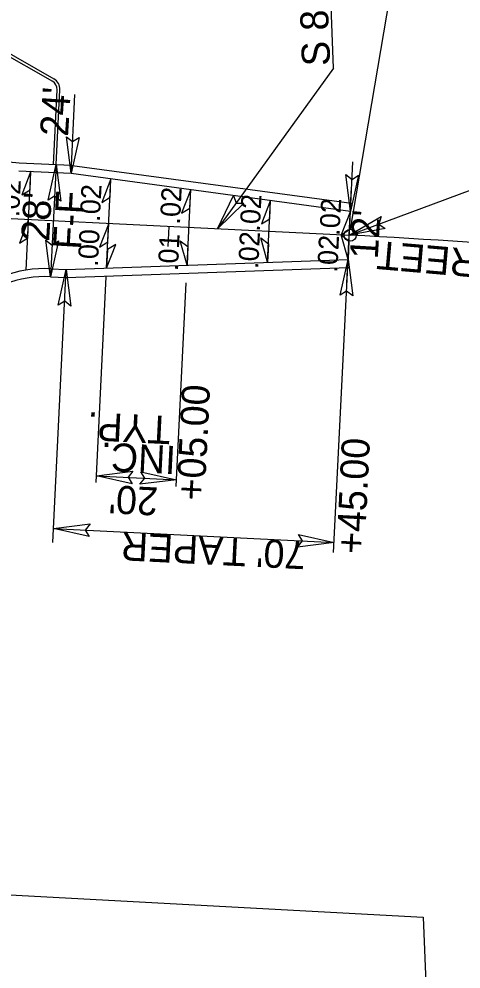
# Model space of a CAD drawing. Extents: x 1627861 to 1629601, y 761281 to 766239.
# Drawn here: x 1628433.8 to 1628544, y 764815.3 to 765051.9 of the extents above; entities that cross this region are included whole.
import ezdxf

# ---------------------------------------------------------------- set-up
doc = ezdxf.new("R2010")
doc.units = 0
for name, color, linetype in [('Cogo Default Point CELL', 7, 'Continuous'), ('Exist Other Culture Sign Leader', 7, 'Continuous'), ('Exist Property Tie Line Text', 7, 'Continuous'), ('Exist Right of Way Line Leader', 7, 'Continuous'), ('Exist Right of Way Monument Text', 7, 'Continuous'), ('Exist Utilities Gas Meter CELL', 7, 'Continuous'), ('Exist Utilities Gas Meter Cogo Elevation', 7, 'Continuous'), ('Exist Utilities Gas Meter Cogo Number', 7, 'Continuous'), ('Exist Utilities Power UG Cable SUE LOS B Cogo Point CELL', 7, 'Continuous'), ('Exist Utilities Telephone UG Cable SUE LOS B Cogo Number', 7, 'Continuous'), ('Exist Utilities Telephone UG Cable SUE LOS B Cogo Point CELL', 7, 'Continuous'), ('Exist Utilities Water UG Line SUE LOS B Cogo Number', 7, 'Continuous'), ('Scratch_Level_0', 7, 'Continuous'), ('Typical Terminator CELL', 7, 'Continuous')]:
    doc.layers.add(name, color=color, linetype=linetype)

msp = doc.modelspace()

# ---------------------------------------------------------------- linework, layer by layer
at = {"layer": 'Exist Property Tie Line Text'}
msp.add_line((1628471.18, 765000.29), (1628470.94, 764995.3), dxfattribs=at)
at = {"layer": 'Exist Right of Way Line Leader'}
for p, q in [((1628512.23, 765039.73), (1628509.44, 765110.32)), ((1628516.43, 764999.57), (1628528.34, 765069.48)), ((1628512.23, 765039.73), (1628483.32, 764999.7)), ((1628379.89, 764836.53), (1628534.55, 764828.18)), ((1628534.55, 764828.18), (1628539.7, 764697.65))]:
    msp.add_line(p, q, dxfattribs=at)
msp.add_circle((1628516.35, 764998.07), 1.5, dxfattribs=at)
at = {"layer": 'Exist Right of Way Monument Text'}
for p, q in [((1628433.78, 765014.15), (1628442.99, 765013.69)), ((1628442.99, 765013.69), (1628446.8, 765013.51)), ((1628446.8, 765013.51), (1628516.42, 765004.09)), ((1628445.62, 764989.53), (1628515.83, 764992.06)), ((1628441.81, 764989.72), (1628445.62, 764989.53))]:
    msp.add_line(p, q, dxfattribs=at)
msp.add_arc((1628440.34, 764959.76), 30, 87.1852, 182.2582, dxfattribs=at)
at = {"layer": 'Exist Utilities Gas Meter CELL'}
msp.add_line((1628371.3, 765005.2), (1628516.35, 764998.07), dxfattribs=at)
msp.add_arc((1628450.06, 763649.7), 1350, 82.22219, 87.18524, dxfattribs=at)
at = {"layer": 'Exist Utilities Gas Meter Cogo Elevation'}
msp.add_line((1628433.87, 765016.14), (1628443.09, 765015.69), dxfattribs=at)
for centre, start, end in [((1628435.25, 765044.11), 185.0968, 267.1852), ((1628440.34, 764959.76), 87.1852, 182.2582)]:
    msp.add_arc(centre, 28, start, end, dxfattribs=at)
at = {"layer": 'Exist Utilities Gas Meter Cogo Number'}
for points in [[(1628448.79, 765022.42), (1628446.8, 765013.51), (1628445.65, 765022.62), (1628447.19, 765021.4)], [(1628441.1, 765006.78), (1628443.09, 765015.69), (1628444.24, 765006.57), (1628442.7, 765007.8)], [(1628518.41, 765013), (1628516.42, 765004.09), (1628515.27, 765013.21), (1628516.81, 765011.98)], [(1628489.84, 765006.08), (1628483.32, 764999.7), (1628487.32, 765007.97), (1628487.94, 765006.1)], [(1628525.1, 764999.77), (1628516.13, 764998.08), (1628524.05, 765002.74), (1628523.53, 765000.84)], [(1628443.7, 764996.64), (1628441.71, 764987.72), (1628440.56, 764996.84), (1628442.1, 764995.61)], [(1628513.84, 764983.15), (1628515.83, 764992.06), (1628516.99, 764982.95), (1628515.44, 764984.17)], [(1628443.63, 764980.62), (1628445.62, 764989.53), (1628446.78, 764980.42), (1628445.23, 764981.64)], [(1628462.02, 764936.17), (1628453.11, 764938.16), (1628462.23, 764939.31), (1628461, 764937.77)], [(1628464.17, 764939.17), (1628473.08, 764937.18), (1628463.97, 764936.02), (1628465.19, 764937.56)], [(1628451.36, 764923), (1628442.45, 764924.99), (1628451.57, 764926.15), (1628450.34, 764924.61)], [(1628503.45, 764923.55), (1628512.37, 764921.56), (1628503.25, 764920.4), (1628504.47, 764921.94)]]:
    msp.add_lwpolyline(points, close=True, dxfattribs=at)
at = {"layer": 'Exist Utilities Telephone UG Cable SUE LOS B Cogo Number'}
for p, q in [((1628425.14, 765046.19), (1628442.16, 765036.47)), ((1628425.47, 765046.77), (1628442.49, 765037.05)), ((1628442.42, 765015.72), (1628443.34, 765034.33)), ((1628443.09, 765015.69), (1628444, 765034.3))]:
    msp.add_line(p, q, dxfattribs=at)
for radius in [2.33, 3]:
    msp.add_arc((1628441.01, 765034.45), radius, 357.1852, 60.2857, dxfattribs=at)
at = {"layer": 'Exist Utilities Telephone UG Cable SUE LOS B Cogo Point CELL'}
for p, q in [((1628443.09, 765015.69), (1628446.9, 765015.5)), ((1628447.07, 765015.49), (1628516.69, 765006.07)), ((1628445.69, 764987.54), (1628515.9, 764990.07)), ((1628441.71, 764987.72), (1628445.52, 764987.54))]:
    msp.add_line(p, q, dxfattribs=at)
at = {"layer": 'Exist Utilities Water UG Line SUE LOS B Cogo Number'}
for p, q in [((1628435.6, 764989.38), (1628436.81, 765014)), ((1628455.65, 764989.9), (1628456.75, 765012.16)), ((1628475.71, 764990.62), (1628476.64, 765009.47)), ((1628495.77, 764991.34), (1628496.53, 765006.78)), ((1628515.83, 764992.06), (1628516.42, 765004.09))]:
    msp.add_line(p, q, dxfattribs=at)
at = {"layer": 'Scratch_Level_0'}
for p, q in [((1628446.8, 765013.51), (1628447.77, 765033.12)), ((1628516.13, 764998.08), (1628577.44, 765020.93)), ((1628443.09, 765015.69), (1628441.71, 764987.72)), ((1628516.42, 765004.09), (1628517.02, 765016.33)), ((1628515.54, 764986.1), (1628516.72, 765010.07)), ((1628512.24, 764919.03), (1628515.83, 764992.06)), ((1628442.28, 764921.5), (1628445.62, 764989.53)), ((1628453.03, 764936.48), (1628455.55, 764987.75)), ((1628473, 764935.45), (1628475.5, 764986.23)), ((1628453.11, 764938.16), (1628473.08, 764937.18)), ((1628442.45, 764924.99), (1628512.37, 764921.56))]:
    msp.add_line(p, q, dxfattribs=at)
at = {"layer": 'Typical Terminator CELL'}
for points in [[(1628436.81, 765014), (1628434.52, 765008.1), (1628436.59, 765009.38)], [(1628456.75, 765012.16), (1628454.46, 765006.27), (1628456.52, 765007.54)], [(1628476.64, 765009.47), (1628474.35, 765003.58), (1628476.41, 765004.85)], [(1628496.53, 765006.78), (1628494.24, 765000.89), (1628496.3, 765002.16)], [(1628516.42, 765004.09), (1628514.13, 764998.2), (1628516.2, 764999.47)], [(1628436.22, 765002.01), (1628433.93, 764996.12), (1628436, 764997.39)], [(1628456.2, 765001.03), (1628453.91, 764995.13), (1628455.97, 764996.41)], [(1628515.83, 764992.06), (1628514.12, 764998.15), (1628516.05, 764996.68)], [(1628455.65, 764989.9), (1628457.94, 764995.79), (1628455.88, 764994.51)], [(1628475.71, 764990.62), (1628474, 764996.71), (1628475.93, 764995.24)], [(1628495.77, 764991.34), (1628494.06, 764997.43), (1628495.99, 764995.96)]]:
    msp.add_lwpolyline(points, close=True, dxfattribs=at)

# ---------------------------------------------------------------- texts
at = {"layer": 'Cogo Default Point CELL'}
msp.add_text('S 87%%d 11\' 06.9" E', height=7, rotation=92.2582, dxfattribs=at).set_placement((1628511.39, 765040.34))
at = {"layer": 'Exist Other Culture Sign Leader'}
msp.add_text('-Y15- EVANS STREET', height=7, rotation=175.0469, dxfattribs=at).set_placement((1628619.76, 764988.3))
at = {"layer": 'Exist Utilities Power UG Cable SUE LOS B Cogo Point CELL'}
for s, rotation, p in [("24'", 86.503, (1628446.04, 765022.56)), ("28'", 86.6116, (1628441.33, 764996.39)), ('F-F', 86.6116, (1628449.26, 764994.38)), ("12'", 86.6116, (1628523.22, 764991.99)), ('+05.00', 87.1852, (1628480.05, 764931.86)), ('TYP.', 177.1852, (1628471.78, 764952.99)), ('INC.', 177.1852, (1628473.06, 764945.54)), ('+45.00', 87.1852, (1628519.89, 764918.57)), ("20'", 177.1852, (1628468.61, 764935.21)), ("70' TAPER", 177.1852, (1628505.37, 764921.84))]:
    msp.add_text(s, height=7, rotation=rotation, dxfattribs=at).set_placement(p)
at = {"layer": 'Exist Utilities Water UG Line SUE LOS B Cogo Number'}
for s, p in [('.02', (1628433.86, 765002.54)), ('.02', (1628453.97, 765001.36)), ('.02', (1628473.94, 765000.67)), ('.02', (1628493.83, 764998.91)), ('.02', (1628513.68, 764997.87)), ('.00', (1628453.48, 764990.17)), ('.01', (1628473.42, 764989.08)), ('.02', (1628493.44, 764989.61)), ('.02', (1628513.14, 764988.71))]:
    msp.add_text(s, height=5, rotation=87.1852, dxfattribs=at).set_placement(p)

doc.saveas('drawing.dxf')
